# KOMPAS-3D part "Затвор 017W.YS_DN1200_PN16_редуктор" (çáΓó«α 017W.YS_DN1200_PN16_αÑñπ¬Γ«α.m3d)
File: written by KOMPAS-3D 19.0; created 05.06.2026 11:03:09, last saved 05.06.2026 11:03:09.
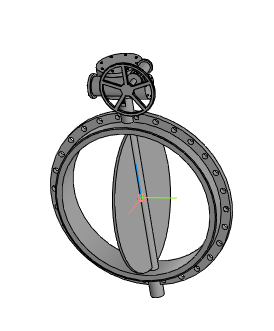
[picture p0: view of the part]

Document properties: Автор: Энергия; Полное имя файла: ..\..\..\3d для проектировщиков\x.x Тип 017W.Y(S) Затвор дисковый поворотный межфланцевый\Затвор 017W.Y(S)_DN50-DN1200_редуктор\Затвор 017W.YS_DN1200_PN16_редуктор.a3d

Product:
- Part/product: Затвор 017W.YS_DN1200_PN16_редуктор
    Масса: 1024.07

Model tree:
1. Операция без истории:1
